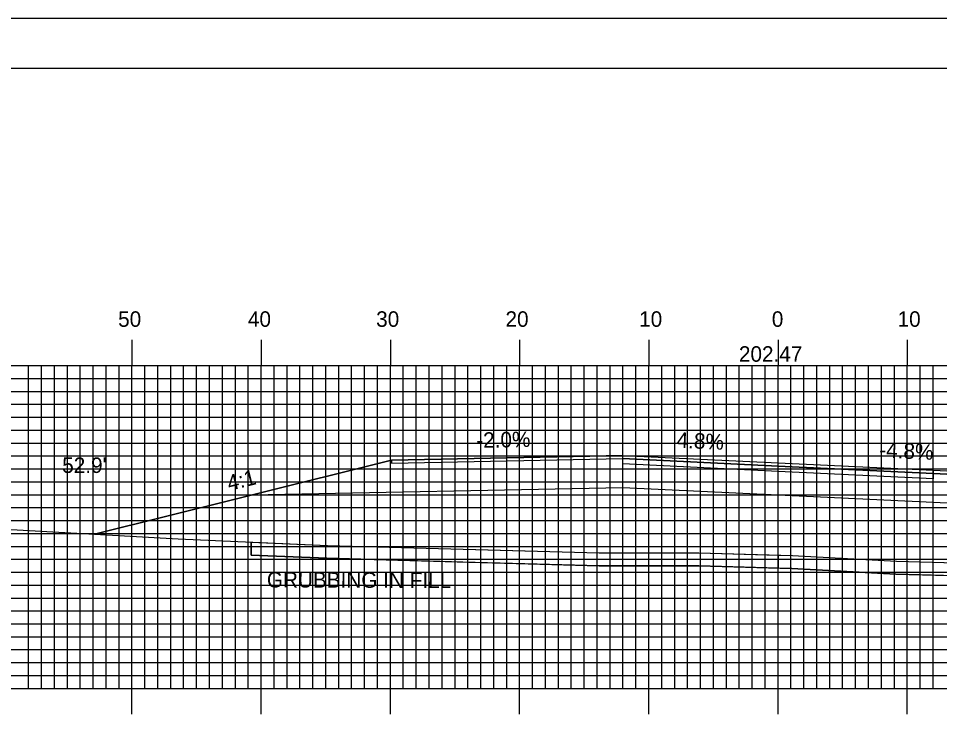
# Model space of a CAD drawing. Extents: x 1813735 to 1814078, y 442591 to 442811.
# Drawn here: x 1813841.7 to 1813913, y 442756.2 to 442810.5 of the extents above; entities that cross this region are included whole.
import ezdxf

# ---------------------------------------------------------------- set-up
doc = ezdxf.new("R2010")
doc.units = 0
for name, color, linetype in [('ANNOTATION', 7, 'Continuous'), ('BORDER', 7, 'Continuous'), ('D_Roadway_Centerline', 7, 'Continuous'), ('D_Roadway_Centerline_Text', 7, 'Continuous'), ('D_Roadway_Edge_Shoulder', 7, 'Continuous'), ('D_Roadway_Edge_TW', 7, 'Continuous'), ('D_Roadway_Pavement', 7, 'Continuous'), ('D_Roadway_SlopeLines', 7, 'Continuous'), ('D_Roadway_SubGrade', 7, 'Continuous'), ('D_Text_Standard', 7, 'Continuous'), ('GRUBBING IN FILL', 7, 'Continuous'), ('H_V ANNOTATION', 7, 'Continuous'), ('MAJOR', 7, 'Continuous'), ('MINOR', 7, 'Continuous'), ('PLOT BOUNDARY', 7, 'Continuous'), ('S_Roadway_Centerline', 7, 'Continuous')]:
    doc.layers.add(name, color=color, linetype=linetype)

msp = doc.modelspace()

# ---------------------------------------------------------------- linework, layer by layer
at = {"layer": 'BORDER'}
msp.add_lwpolyline([(1813750.881, 442596.665), (1814070.881, 442596.665), (1814070.881, 442806.665), (1813750.881, 442806.665)], close=True, dxfattribs=at)
at = {"layer": 'D_Roadway_Centerline'}
msp.add_lwpolyline([(1813847.582, 442770.602), (1813858.576, 442773.351), (1813859.706, 442773.633), (1813870.576, 442776.351), (1813888.481, 442776.709), (1813900.481, 442776.133), (1813912.481, 442775.557), (1813920.481, 442775.173), (1813932.858, 442772.079), (1813951.298, 442767.468)], dxfattribs=at)
at = {"layer": 'D_Roadway_Edge_Shoulder'}
for points in [[(1813888.481, 442776.709), (1813870.576, 442776.351), (1813870.576, 442776.101), (1813888.481, 442776.459)], [(1813912.481, 442775.557), (1813920.481, 442775.173), (1813920.481, 442774.923), (1813912.481, 442775.307)]]:
    msp.add_lwpolyline(points, close=True, dxfattribs=at)
at = {"layer": 'D_Roadway_Edge_TW'}
msp.add_lwpolyline([(1813888.481, 442776.459), (1813888.481, 442776.709), (1813900.481, 442776.133), (1813912.481, 442775.557), (1813912.481, 442775.307), (1813900.481, 442775.883)], close=True, dxfattribs=at)
at = {"layer": 'D_Roadway_Pavement'}
msp.add_lwpolyline([(1813888.481, 442776.042), (1813888.481, 442776.459), (1813900.481, 442775.883), (1813912.481, 442775.307), (1813912.481, 442774.89), (1813900.481, 442775.466)], close=True, dxfattribs=at)
at = {"layer": 'D_Roadway_SlopeLines'}
msp.add_lwpolyline([(1813870.576, 442776.351), (1813859.706, 442773.633), (1813858.576, 442773.351), (1813847.582, 442770.602)], dxfattribs=at)
at = {"layer": 'D_Roadway_SubGrade'}
msp.add_lwpolyline([(1813888.481, 442774.209), (1813859.706, 442773.633), (1813870.576, 442776.351), (1813870.576, 442776.101), (1813888.481, 442776.459), (1813900.481, 442775.883), (1813912.481, 442775.307), (1813920.481, 442774.923), (1813920.481, 442775.173), (1813932.858, 442772.079), (1813912.481, 442773.057), (1813900.481, 442773.633)], close=True, dxfattribs=at)
at = {"layer": 'GRUBBING IN FILL'}
msp.add_line((1813859.706, 442769.991), (1813859.706, 442768.99), dxfattribs=at)
msp.add_line((1813859.706, 442769.991), (1813859.706, 442768.99), dxfattribs=at)
for points in [[(1813859.706, 442769.991), (1813865.606, 442769.738), (1813876.123, 442769.45), (1813886.639, 442769.162), (1813894.359, 442769.164), (1813900.481, 442768.986), (1813900.481, 442767.986), (1813894.344, 442768.164), (1813886.626, 442768.162), (1813876.099, 442768.45), (1813865.571, 442768.739), (1813859.706, 442768.99)], [(1813859.706, 442769.991), (1813865.606, 442769.738), (1813876.123, 442769.45), (1813886.639, 442769.162), (1813894.359, 442769.164), (1813900.481, 442768.986), (1813900.481, 442767.986), (1813894.344, 442768.164), (1813886.626, 442768.162), (1813876.099, 442768.45), (1813865.571, 442768.739), (1813859.706, 442768.99)], [(1813900.481, 442768.986), (1813901.59, 442768.954), (1813909.643, 442768.513), (1813914.247, 442768.392), (1813918.85, 442768.271), (1813923.419, 442768.145), (1813927.987, 442768.019), (1813932.858, 442767.884), (1813932.858, 442766.884), (1813927.96, 442767.019), (1813923.392, 442767.146), (1813918.824, 442767.272), (1813914.213, 442767.393), (1813909.602, 442767.514), (1813901.548, 442767.955), (1813900.481, 442767.986)], [(1813900.481, 442768.986), (1813901.59, 442768.954), (1813909.643, 442768.513), (1813914.247, 442768.392), (1813918.85, 442768.271), (1813923.419, 442768.145), (1813927.987, 442768.019), (1813932.858, 442767.884), (1813932.858, 442766.884), (1813927.96, 442767.019), (1813923.392, 442767.146), (1813918.824, 442767.272), (1813914.213, 442767.393), (1813909.602, 442767.514), (1813901.548, 442767.955), (1813900.481, 442767.986)]]:
    msp.add_lwpolyline(points, close=True, dxfattribs=at)
msp.add_lwpolyline([(1813859.706, 442768.99), (1813865.571, 442768.739), (1813886.626, 442768.162), (1813894.344, 442768.164), (1813901.548, 442767.955), (1813909.602, 442767.514), (1813918.824, 442767.272), (1813927.96, 442767.019), (1813932.858, 442766.884)], dxfattribs=at)
msp.add_lwpolyline([(1813859.706, 442768.99), (1813865.571, 442768.739), (1813886.626, 442768.162), (1813894.344, 442768.164), (1813901.548, 442767.955), (1813909.602, 442767.514), (1813918.824, 442767.272), (1813927.96, 442767.019), (1813932.858, 442766.884)], dxfattribs=at)
at = {"layer": 'MAJOR'}
for p, q in [((1813850.481, 442785.669), (1813850.481, 442783.665)), ((1813860.481, 442785.669), (1813860.481, 442783.665)), ((1813870.481, 442785.669), (1813870.481, 442783.665)), ((1813880.481, 442785.669), (1813880.481, 442783.665)), ((1813890.481, 442785.669), (1813890.481, 442783.665)), ((1813900.481, 442785.669), (1813900.481, 442783.665)), ((1813910.481, 442785.669), (1813910.481, 442783.665)), ((1813760.481, 442783.665), (1814040.481, 442783.665)), ((1813760.481, 442783.665), (1814040.481, 442783.665)), ((1813850.481, 442758.665), (1813850.481, 442783.665)), ((1813860.481, 442758.665), (1813860.481, 442783.665)), ((1813870.481, 442758.665), (1813870.481, 442783.665)), ((1813880.481, 442758.665), (1813880.481, 442783.665)), ((1813890.481, 442758.665), (1813890.481, 442783.665)), ((1813900.481, 442758.665), (1813900.481, 442783.665)), ((1813910.481, 442758.665), (1813910.481, 442783.665)), ((1813760.481, 442778.665), (1814040.481, 442778.665)), ((1813760.481, 442773.665), (1814040.481, 442773.665)), ((1813760.481, 442768.665), (1814040.481, 442768.665)), ((1813760.481, 442763.665), (1814040.481, 442763.665)), ((1813760.481, 442758.665), (1814040.481, 442758.665)), ((1813760.481, 442758.665), (1814040.481, 442758.665)), ((1813850.481, 442756.661), (1813850.481, 442758.665)), ((1813860.481, 442756.661), (1813860.481, 442758.665)), ((1813870.481, 442756.661), (1813870.481, 442758.665)), ((1813880.481, 442756.661), (1813880.481, 442758.665)), ((1813890.481, 442756.661), (1813890.481, 442758.665)), ((1813900.481, 442756.661), (1813900.481, 442758.665)), ((1813910.481, 442756.661), (1813910.481, 442758.665))]:
    msp.add_line(p, q, dxfattribs=at)
at = {"layer": 'MINOR'}
for p, q in [((1813842.481, 442758.665), (1813842.481, 442783.665)), ((1813843.481, 442758.665), (1813843.481, 442783.665)), ((1813844.481, 442758.665), (1813844.481, 442783.665)), ((1813845.481, 442758.665), (1813845.481, 442783.665)), ((1813846.481, 442758.665), (1813846.481, 442783.665)), ((1813847.481, 442758.665), (1813847.481, 442783.665)), ((1813848.481, 442758.665), (1813848.481, 442783.665)), ((1813849.481, 442758.665), (1813849.481, 442783.665)), ((1813851.481, 442758.665), (1813851.481, 442783.665)), ((1813852.481, 442758.665), (1813852.481, 442783.665)), ((1813853.481, 442758.665), (1813853.481, 442783.665)), ((1813854.481, 442758.665), (1813854.481, 442783.665)), ((1813855.481, 442758.665), (1813855.481, 442783.665)), ((1813856.481, 442758.665), (1813856.481, 442783.665)), ((1813857.481, 442758.665), (1813857.481, 442783.665)), ((1813858.481, 442758.665), (1813858.481, 442783.665)), ((1813859.481, 442758.665), (1813859.481, 442783.665)), ((1813861.481, 442758.665), (1813861.481, 442783.665)), ((1813862.481, 442758.665), (1813862.481, 442783.665)), ((1813863.481, 442758.665), (1813863.481, 442783.665)), ((1813864.481, 442758.665), (1813864.481, 442783.665)), ((1813865.481, 442758.665), (1813865.481, 442783.665)), ((1813866.481, 442758.665), (1813866.481, 442783.665)), ((1813867.481, 442758.665), (1813867.481, 442783.665)), ((1813868.481, 442758.665), (1813868.481, 442783.665)), ((1813869.481, 442758.665), (1813869.481, 442783.665)), ((1813871.481, 442758.665), (1813871.481, 442783.665)), ((1813872.481, 442758.665), (1813872.481, 442783.665)), ((1813873.481, 442758.665), (1813873.481, 442783.665)), ((1813874.481, 442758.665), (1813874.481, 442783.665)), ((1813875.481, 442758.665), (1813875.481, 442783.665)), ((1813876.481, 442758.665), (1813876.481, 442783.665)), ((1813877.481, 442758.665), (1813877.481, 442783.665)), ((1813878.481, 442758.665), (1813878.481, 442783.665)), ((1813879.481, 442758.665), (1813879.481, 442783.665)), ((1813881.481, 442758.665), (1813881.481, 442783.665)), ((1813882.481, 442758.665), (1813882.481, 442783.665)), ((1813883.481, 442758.665), (1813883.481, 442783.665)), ((1813884.481, 442758.665), (1813884.481, 442783.665)), ((1813885.481, 442758.665), (1813885.481, 442783.665)), ((1813886.481, 442758.665), (1813886.481, 442783.665)), ((1813887.481, 442758.665), (1813887.481, 442783.665)), ((1813888.481, 442758.665), (1813888.481, 442783.665)), ((1813889.481, 442758.665), (1813889.481, 442783.665)), ((1813891.481, 442758.665), (1813891.481, 442783.665)), ((1813892.481, 442758.665), (1813892.481, 442783.665)), ((1813893.481, 442758.665), (1813893.481, 442783.665)), ((1813894.481, 442758.665), (1813894.481, 442783.665)), ((1813895.481, 442758.665), (1813895.481, 442783.665)), ((1813896.481, 442758.665), (1813896.481, 442783.665)), ((1813897.481, 442758.665), (1813897.481, 442783.665)), ((1813898.481, 442758.665), (1813898.481, 442783.665)), ((1813899.481, 442758.665), (1813899.481, 442783.665)), ((1813901.481, 442758.665), (1813901.481, 442783.665)), ((1813902.481, 442758.665), (1813902.481, 442783.665)), ((1813903.481, 442758.665), (1813903.481, 442783.665)), ((1813904.481, 442758.665), (1813904.481, 442783.665)), ((1813905.481, 442758.665), (1813905.481, 442783.665)), ((1813906.481, 442758.665), (1813906.481, 442783.665)), ((1813907.481, 442758.665), (1813907.481, 442783.665)), ((1813908.481, 442758.665), (1813908.481, 442783.665)), ((1813909.481, 442758.665), (1813909.481, 442783.665)), ((1813911.481, 442758.665), (1813911.481, 442783.665)), ((1813912.481, 442758.665), (1813912.481, 442783.665)), ((1813760.481, 442782.665), (1814040.481, 442782.665)), ((1813760.481, 442781.665), (1814040.481, 442781.665)), ((1813760.481, 442780.665), (1814040.481, 442780.665)), ((1813760.481, 442779.665), (1814040.481, 442779.665)), ((1813760.481, 442777.665), (1814040.481, 442777.665)), ((1813760.481, 442776.665), (1814040.481, 442776.665)), ((1813760.481, 442775.665), (1814040.481, 442775.665)), ((1813760.481, 442774.665), (1814040.481, 442774.665)), ((1813760.481, 442772.665), (1814040.481, 442772.665)), ((1813760.481, 442771.665), (1814040.481, 442771.665)), ((1813760.481, 442770.665), (1814040.481, 442770.665)), ((1813760.481, 442769.665), (1814040.481, 442769.665)), ((1813760.481, 442767.665), (1814040.481, 442767.665)), ((1813760.481, 442766.665), (1814040.481, 442766.665)), ((1813760.481, 442765.665), (1814040.481, 442765.665)), ((1813760.481, 442764.665), (1814040.481, 442764.665)), ((1813760.481, 442762.665), (1814040.481, 442762.665)), ((1813760.481, 442761.665), (1814040.481, 442761.665)), ((1813760.481, 442760.665), (1814040.481, 442760.665)), ((1813760.481, 442759.665), (1814040.481, 442759.665))]:
    msp.add_line(p, q, dxfattribs=at)
at = {"layer": 'PLOT BOUNDARY'}
msp.add_lwpolyline([(1813734.695, 442590.547), (1814074.695, 442590.547), (1814074.695, 442810.547), (1813734.695, 442810.547)], close=True, dxfattribs=at)
at = {"layer": 'S_Roadway_Centerline'}
msp.add_lwpolyline([(1813760.481, 442772.658), (1813778.12, 442772.108), (1813786.673, 442771.815), (1813787.255, 442771.821), (1813803.277, 442771.39), (1813803.782, 442771.385), (1813818.393, 442771.203), (1813820.441, 442771.082), (1813833.26, 442771.042), (1813836.687, 442770.969), (1813841.594, 442770.943), (1813854.064, 442770.234), (1813865.606, 442769.738), (1813886.639, 442769.162), (1813894.359, 442769.164), (1813901.59, 442768.954), (1813909.643, 442768.513), (1813918.85, 442768.271), (1813927.987, 442768.019), (1813934.696, 442767.833), (1813945.689, 442767.6), (1813951.787, 442767.457), (1813956.334, 442767.229), (1813968.35, 442766.36)], dxfattribs=at)

# ---------------------------------------------------------------- texts
at = {"layer": 'ANNOTATION'}
for s, rotation, p in [('-2.0%', 1.14576, (1813877.135, 442777.282)), ('4.8%', 357.25191, (1813892.61, 442777.313)), ('-4.8%', 357.25191, (1813908.29, 442776.56)), ('4:1', 14.03624, (1813858.01, 442773.95))]:
    msp.add_text(s, height=1.2, rotation=rotation, dxfattribs=at).set_placement(p)
at = {"layer": 'D_Roadway_Centerline'}
for s, p in [('C', (1813900.476, 442776.133)), ('L', (1813900.481, 442776.125))]:
    msp.add_text(s, height=0.0146, dxfattribs=at).set_placement(p)
at = {"layer": 'D_Roadway_Centerline_Text'}
msp.add_text('202.47', height=1.2, dxfattribs=at).set_placement((1813897.453, 442783.961))
at = {"layer": 'D_Text_Standard'}
msp.add_text("52.9'", height=1.2, dxfattribs=at).set_placement((1813845.083, 442775.348))
at = {"layer": 'GRUBBING IN FILL'}
msp.add_text('GRUBBING IN FILL', height=1.2, rotation=359.80532, dxfattribs=at).set_placement((1813860.918, 442766.484))
at = {"layer": 'H_V ANNOTATION'}
for s, p in [('50', (1813849.411, 442786.665)), ('40', (1813859.454, 442786.665)), ('30', (1813869.379, 442786.665)), ('20', (1813879.389, 442786.665)), ('10', (1813889.732, 442786.665)), ('0', (1813899.999, 442786.665)), ('10', (1813909.732, 442786.665))]:
    msp.add_text(s, height=1.2, dxfattribs=at).set_placement(p)

doc.saveas('drawing.dxf')
